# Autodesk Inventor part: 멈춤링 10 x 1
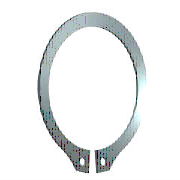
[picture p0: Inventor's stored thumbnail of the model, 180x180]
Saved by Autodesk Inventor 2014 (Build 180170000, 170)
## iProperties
IsCustomPart: 0
Company: 한국ATC센터
Created: 2009-02
Part Number: 멈춤링 10 x 1
Material: Steel, Mild
Description: 리테이닝 링(C형)
Document SubType Name: Modeling
Standard: KS B 1336
Designer: KYOUNG IL JANG
Standards Organization: KS
Language: ko-KR
Size Designation: 10 x 1
Categories: <MemberInstance><Categories><Category DisplayName="샤프트 부품" InternalName="7f7aeb1f-a693-4053-b835-cee3144e0d98" Mnemonic="SHFT"><Category DisplayName="써클립" Inter
Density: 7.86 g/cm^3
Mass: 0.423084 g
Surface Area: 1.9243 cm^2
Volume: 0.0538275 cm^3
Appearance: Metal-Steel
Author: KYOUNG IL JANG
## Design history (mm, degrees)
sketch "스케치1"
  geometry: L1 (-6, 0)-(6, 0) reference; L2 (0, 20.189)-(0, -80.536) reference; L3 (-48.09, 0)-(48.09, 0) reference; L4 (-0.3, -9.791)-(-0.3, -12.791); L5 (-0.3, -6.54)-(-0.3, -13.29); L6 (-2.795, 1.6)-(3.672, 1.6); L7 (0.3, -6.54)-(0.3, -13.29); L8 (0.3, -9.791)-(0.3, -12.791); C1 r 0.6 at (-1.2, -11.486); C2 r 0.6 at (1.2, -11.486); A1 r 4.8 centre (0, -5) between (0.3, -9.791) and (-0.3, -9.791); A2 r 6.2 centre (0, -4.6) between (2.988, -10.033) and (-2.988, -10.033); A3 r 7.796 centre (0, -5) between (-1.418, -12.666) and (-0.3, -12.791); A4 r 1.2 centre (-1.2, -11.486) between (-2.383, -11.285) and (-1.418, -12.666); A5 r 1.2 centre (-3.566, -11.084) between (-2.383, -11.285) and (-2.988, -10.033); A6 r 1.2 centre (3.566, -11.084) between (2.988, -10.033) and (2.383, -11.285); A7 r 1.2 centre (1.2, -11.486) between (1.418, -12.666) and (2.383, -11.285); A8 r 7.796 centre (0, -5) between (0.3, -12.791) and (1.418, -12.666)
  constraints: 16 point on circle, 12 end point, 10 centre point, 9 symmetric about line, 5 point on line, 4 tangent, 3 coincident, 2 horizontal, 1 perpendicular, 1 vertical, 5 other
  dimensions: "d0" = 9.6 diameter of A1 (= ND); "d1" = 3 distance of L4.end L4.start (= SRB2); "d6" = 0.3 distance between parallel lines of L2 L5 (= 0.25 x SD5); "d7" = 1.6 distance between parallel lines of L6 L3 (= SRB1); "d8" = 0.4 distance of A1.centre A2.centre (= 0.25 x SRB1); "d9" = 1.2 radius of A4 (= SD5); "d10" = 1.2 radius of A5 (= SD5); "d11" = 0.9 distance from line of L4 A4.centre (= 0.75 x SD5); "d12" = 1.2 diameter of C1 (= SD5); "d13" = 1.2 diameter of C2 (= SD5); "d14" = 5 distance from line of A1.centre L1 (= 0.5 x WD)
extrude "본체" new body sketch "스케치1" distance "d2" = 1 (= SD); taper "d3" = 0 deg
workaxis "Work Axis1"
workplane "Work Plane1"
body "Solid1"
other parameters: "SD" = 1 [user parameter; used in 1 equation term], "SRB1" = 1.6 [user parameter; used in 2 equation terms], "ND" = 9.6 [user parameter; used in 1 equation term], "SRB2" = 3 [user parameter; used in 1 equation term], "SD5" = 1.2 [user parameter; used in 6 equation terms], "d15" = 0, "d16" = 0, "d17" = 0, "d41" = 0, "d42" = 0, "SD3" = 9.3 [user parameter], "WDMAX" = 11 [user parameter]
